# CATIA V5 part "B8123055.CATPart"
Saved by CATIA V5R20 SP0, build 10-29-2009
Part number: B8123055
Revision: 8
Definition: design
Nomenclature: B8123055
Source: made
Description: NOT SPECIFIED
Bounding box of the stored display mesh (mm): x -26 to 26, y -26 to 26, z -21 to 34
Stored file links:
  C:\Users\Utente\Desktop\3D files B812\B8123055.CATPart
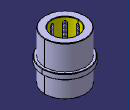
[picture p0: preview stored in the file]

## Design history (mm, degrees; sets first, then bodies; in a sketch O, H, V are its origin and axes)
Body1 "MANIFOLD_SOLID_BREP #38" (main body)
  Solid1: solid without history
Body2 "MANIFOLD_SOLID_BREP #76"
  Solid2: solid without history
Body3 "MANIFOLD_SOLID_BREP #114"
  Solid3: solid without history
Body4 "MANIFOLD_SOLID_BREP #152"
  Solid4: solid without history
Body5 "MANIFOLD_SOLID_BREP #190"
  Solid5: solid without history
Body6 "MANIFOLD_SOLID_BREP #228"
  Solid6: solid without history
Body7 "MANIFOLD_SOLID_BREP #266"
  Solid7: solid without history
Body8 "MANIFOLD_SOLID_BREP #304"
  Solid8: solid without history
Body9 "MANIFOLD_SOLID_BREP #2384"
  Solid9: solid without history
Body10 "MANIFOLD_SOLID_BREP #2422"
  Solid10: solid without history
Body11 "MANIFOLD_SOLID_BREP #2460"
  Solid11: solid without history
Body12 "MANIFOLD_SOLID_BREP #2498"
  Solid12: solid without history
Body13 "MANIFOLD_SOLID_BREP #2536"
  Solid13: solid without history
Body14 "MANIFOLD_SOLID_BREP #2574"
  Solid14: solid without history
Body15 "MANIFOLD_SOLID_BREP #2612"
  Solid15: solid without history
Body16 "MANIFOLD_SOLID_BREP #2650"
  Solid16: solid without history
Body17 "MANIFOLD_SOLID_BREP #2688"
  Solid17: solid without history
Body18 "MANIFOLD_SOLID_BREP #2726"
  Solid18: solid without history
Body19 "MANIFOLD_SOLID_BREP #2764"
  Solid19: solid without history
Body20 "MANIFOLD_SOLID_BREP #2802"
  Solid20: solid without history
Body21 "MANIFOLD_SOLID_BREP #2840"
  Solid21: solid without history
Body22 "MANIFOLD_SOLID_BREP #2878"
  Solid22: solid without history
Body23 "MANIFOLD_SOLID_BREP #2916"
  Solid23: solid without history
Body24 "MANIFOLD_SOLID_BREP #2954"
  Solid24: solid without history
Body25 "MANIFOLD_SOLID_BREP #2992"
  Solid25: solid without history
Body26 "MANIFOLD_SOLID_BREP #3030"
  Solid26: solid without history
Body27 "MANIFOLD_SOLID_BREP #3068"
  Solid27: solid without history
Body28 "MANIFOLD_SOLID_BREP #3106"
  Solid28: solid without history
Body29 "MANIFOLD_SOLID_BREP #3144"
  Solid29: solid without history
Body30 "MANIFOLD_SOLID_BREP #3182"
  Solid30: solid without history
Body31 "MANIFOLD_SOLID_BREP #3220"
  Solid31: solid without history
Body32 "MANIFOLD_SOLID_BREP #3258"
  Solid32: solid without history
Body33 "MANIFOLD_SOLID_BREP #3296"
  Solid33: solid without history
Body34 "MANIFOLD_SOLID_BREP #3334"
  Solid34: solid without history
Body35 "MANIFOLD_SOLID_BREP #3372"
  Solid35: solid without history
Body36 "MANIFOLD_SOLID_BREP #3410"
  Solid36: solid without history
Body37 "MANIFOLD_SOLID_BREP #3448"
  Solid37: solid without history
Body38 "MANIFOLD_SOLID_BREP #3486"
  Solid38: solid without history
Body39 "MANIFOLD_SOLID_BREP #3524"
  Solid39: solid without history
Body40 "MANIFOLD_SOLID_BREP #3562"
  Solid40: solid without history
Body41 "MANIFOLD_SOLID_BREP #3600"
  Solid41: solid without history
Body42 "MANIFOLD_SOLID_BREP #3638"
  Solid42: solid without history
Body43 "MANIFOLD_SOLID_BREP #3676"
  Solid43: solid without history
Body44 "MANIFOLD_SOLID_BREP #3714"
  Solid44: solid without history
Body45 "MANIFOLD_SOLID_BREP #3752"
  Solid45: solid without history
Body46 "MANIFOLD_SOLID_BREP #3790"
  Solid46: solid without history
Body47 "MANIFOLD_SOLID_BREP #3828"
  Solid47: solid without history
Body48 "MANIFOLD_SOLID_BREP #3866"
  Solid48: solid without history
Body49 "MANIFOLD_SOLID_BREP #3904"
  Solid49: solid without history
Body50 "MANIFOLD_SOLID_BREP #3942"
  Solid50: solid without history
Body51 "MANIFOLD_SOLID_BREP #3980"
  Solid51: solid without history
Body52 "MANIFOLD_SOLID_BREP #4018"
  Solid52: solid without history
Body53 "MANIFOLD_SOLID_BREP #4056"
  Solid53: solid without history
Body54 "MANIFOLD_SOLID_BREP #4094"
  Solid54: solid without history
Body55 "MANIFOLD_SOLID_BREP #4132"
  Solid55: solid without history
Body56 "MANIFOLD_SOLID_BREP #4170"
  Solid56: solid without history
Body57 "MANIFOLD_SOLID_BREP #4208"
  Solid57: solid without history
Body58 "MANIFOLD_SOLID_BREP #4246"
  Solid58: solid without history
Body59 "MANIFOLD_SOLID_BREP #4284"
  Solid59: solid without history
Body60 "MANIFOLD_SOLID_BREP #4322"
  Solid60: solid without history
Body61 "MANIFOLD_SOLID_BREP #4360"
  Solid61: solid without history
Body62 "MANIFOLD_SOLID_BREP #4398"
  Solid62: solid without history
Body63 "MANIFOLD_SOLID_BREP #4436"
  Solid63: solid without history
Body64 "MANIFOLD_SOLID_BREP #4474"
  Solid64: solid without history
Body65 "MANIFOLD_SOLID_BREP #4512"
  Solid65: solid without history
Body66 "MANIFOLD_SOLID_BREP #4550"
  Solid66: solid without history
Body67 "MANIFOLD_SOLID_BREP #4588"
  Solid67: solid without history
Body68 "MANIFOLD_SOLID_BREP #4626"
  Solid68: solid without history
Body69 "MANIFOLD_SOLID_BREP #4664"
  Solid69: solid without history
Body70 "MANIFOLD_SOLID_BREP #4702"
  Solid70: solid without history
Body71 "MANIFOLD_SOLID_BREP #4740"
  Solid71: solid without history
Body72 "MANIFOLD_SOLID_BREP #4778"
  Solid72: solid without history
Body73 "MANIFOLD_SOLID_BREP #4816"
  Solid73: solid without history
Body74 "MANIFOLD_SOLID_BREP #4854"
  Solid74: solid without history
Body75 "MANIFOLD_SOLID_BREP #4892"
  Solid75: solid without history
Body76 "MANIFOLD_SOLID_BREP #4930"
  Solid76: solid without history
Body77 "MANIFOLD_SOLID_BREP #4968"
  Solid77: solid without history
Body78 "MANIFOLD_SOLID_BREP #5006"
  Solid78: solid without history
Body79 "MANIFOLD_SOLID_BREP #5044"
  Solid79: solid without history
Body80 "MANIFOLD_SOLID_BREP #5082"
  Solid80: solid without history
Body81 "MANIFOLD_SOLID_BREP #5120"
  Solid81: solid without history
Body82 "MANIFOLD_SOLID_BREP #5158"
  Solid82: solid without history
Body83 "MANIFOLD_SOLID_BREP #5196"
  Solid83: solid without history
Body84 "MANIFOLD_SOLID_BREP #5234"
  Solid84: solid without history
Body85 "MANIFOLD_SOLID_BREP #5272"
  Solid85: solid without history
Body86 "MANIFOLD_SOLID_BREP #5310"
  Solid86: solid without history
Body87 "MANIFOLD_SOLID_BREP #5348"
  Solid87: solid without history
Body88 "MANIFOLD_SOLID_BREP #5386"
  Solid88: solid without history
Body89 "MANIFOLD_SOLID_BREP #5424"
  Solid89: solid without history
